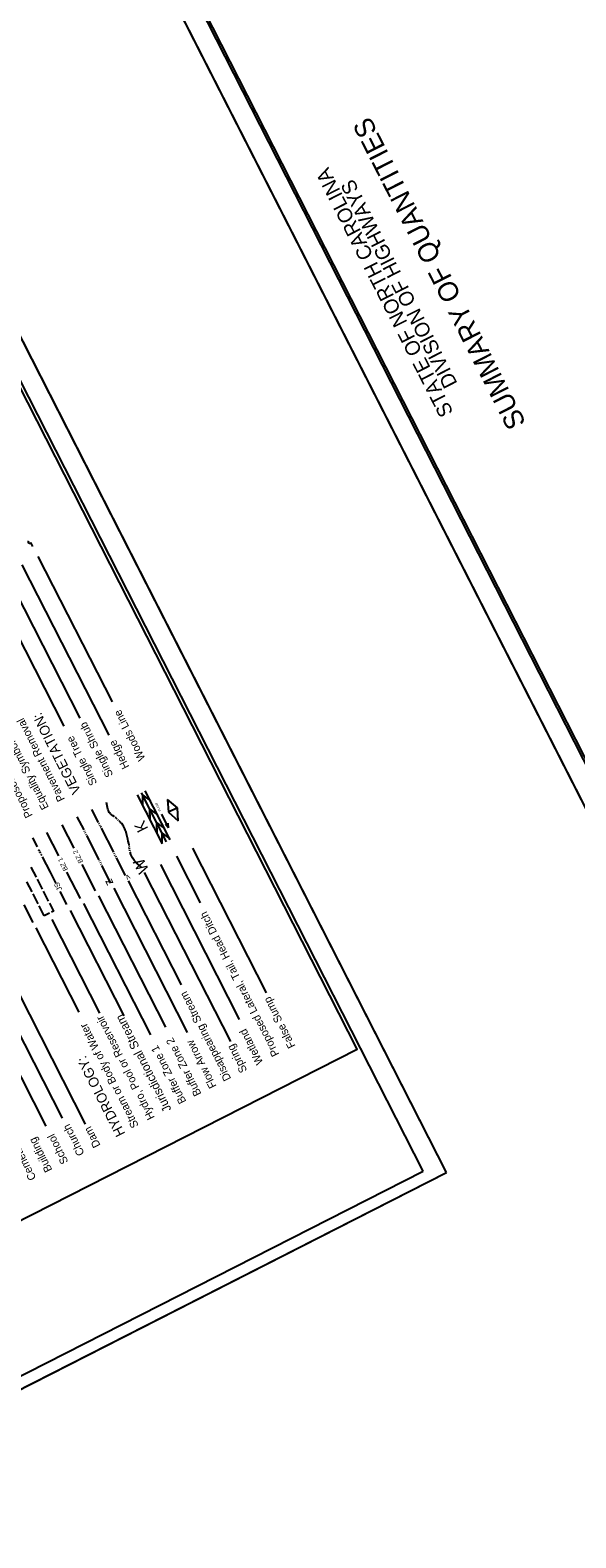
# Model space of a CAD drawing. Extents: x 558484 to 564063, y 513718 to 518374.
# Drawn here: x 561017 to 561623, y 515102 to 516777 of the extents above; entities that cross this region are included whole.
import ezdxf

# ---------------------------------------------------------------- set-up
doc = ezdxf.new("R2010")
doc.units = 0
for name, color, linetype in [('Sheet Cutting Line CELL', 7, 'Continuous'), ('Sheet Plot Border Inside CELL', 7, 'Continuous'), ('Sheet Plot Border Outside CELL', 7, 'Continuous'), ('Sheet Summary CELL', 7, 'Continuous'), ('Sheet Symbology CELL', 7, 'Continuous')]:
    doc.layers.add(name, color=color, linetype=linetype)

msp = doc.modelspace()

# ---------------------------------------------------------------- linework, layer by layer
at = {"layer": 'Sheet Cutting Line CELL'}
for p, q in [((561017.5, 517122.6), (561781.6, 515621.9)), ((561479.4, 515508), (560715.3, 517008.7)), ((560499.1, 515008.9), (561479.4, 515508))]:
    msp.add_line(p, q, dxfattribs=at)
at = {"layer": 'Sheet Plot Border Inside CELL'}
for points in [[(561039.6, 517128.8), (561795.7, 515643.7), (562735.9, 516122.4), (561979.8, 517607.5)], [(561453.5, 515509.4), (560697.4, 516994.5), (559757.1, 516515.8), (560513.2, 515030.7)]]:
    msp.add_lwpolyline(points, close=True, dxfattribs=at)
at = {"layer": 'Sheet Plot Border Outside CELL'}
for points in [[(561017.5, 517122.6), (561781.6, 515621.9), (562761.8, 516121), (561997.8, 517621.7)], [(561479.4, 515508), (560715.3, 517008.7), (559735.1, 516509.6), (560499.1, 515008.9)]]:
    msp.add_lwpolyline(points, close=True, dxfattribs=at)
at = {"layer": 'Sheet Summary CELL'}
msp.add_line((561467.1, 516490.3), (561467.1, 516490.3), dxfattribs=at)
msp.add_lwpolyline([(561047.5, 517118.8), (561728.1, 515782.1), (562663.8, 516258.4), (561983.2, 517595.2)], close=True, dxfattribs=at)
at = {"layer": 'Sheet Symbology CELL'}
for p, q in [((561020.5, 516203.4), (561018.2, 516207.8)), ((561008.3, 516183.2), (561104.8, 515993.7)), ((561026.1, 516192.3), (561108.3, 516030.9)), ((560972.7, 516165.1), (561054.8, 516003.7)), ((560990.5, 516174.2), (561072.7, 516012.8)), ((561168.8, 515875.3), (561141, 515929.9)), ((561172.8, 515877.6), (561145.1, 515932)), ((561164.4, 515873.3), (561136.7, 515927.7)), ((561142.5, 515916.4), (561142.4, 515927.1)), ((561142.4, 515927.1), (561150.8, 515920.9)), ((561180.8, 515913.2), (561169.8, 515922.5)), ((561169.8, 515922.5), (561171, 515908.2)), ((561180.8, 515913.2), (561171, 515908.2)), ((561181.8, 515898.5), (561180.8, 515913.2)), ((561077.2, 515888.5), (561069.7, 515903.1)), ((561093.3, 515896.7), (561085.9, 515911.4)), ((561094.2, 515894.9), (561093.8, 515895.8)), ((561114.1, 515900.6), (561113.3, 515901.2)), ((561115.6, 515899.2), (561114.8, 515899.9)), ((561150.5, 515900.6), (561150.4, 515911.5)), ((561150.4, 515911.5), (561158.8, 515905.2)), ((561158.2, 515885.5), (561158.1, 515896.4)), ((561158.1, 515896.4), (561166.5, 515890)), ((561171.1, 515891), (561163.5, 515905.9)), ((561171.1, 515891), (561170.6, 515896.2)), ((561171, 515908.2), (561181.8, 515898.5)), ((561035.7, 515885.8), (561049, 515859.7)), ((561052.6, 515894.4), (561065.9, 515868.3)), ((561078.1, 515886.7), (561077.6, 515887.6)), ((561079, 515884.9), (561078.5, 515885.8)), ((561079.9, 515883.1), (561079.5, 515884)), ((561094, 515855.5), (561080.4, 515882.2)), ((561095.1, 515893.1), (561094.7, 515894)), ((561096.1, 515891.3), (561095.6, 515892.2)), ((561110.1, 515863.7), (561096.5, 515890.4)), ((561164, 515874.1), (561163.8, 515885)), ((561163.8, 515885), (561172.3, 515878.7)), ((561171.1, 515891), (561167.7, 515894.7)), ((561111, 515861.9), (561110.6, 515862.8)), ((561127.6, 515869.2), (561127.4, 515870.2)), ((561197.5, 515868.3), (561279.3, 515707.7)), ((561018.3, 515847.3), (561023.9, 515836.1)), ((561090, 515820.9), (561075.2, 515850.1)), ((561094.9, 515853.7), (561094.4, 515854.6)), ((561095.8, 515851.9), (561095.3, 515852.8)), ((561096.7, 515850.1), (561096.2, 515851)), ((561107.1, 515829.6), (561097.1, 515849.2)), ((561111.9, 515860.1), (561111.5, 515861)), ((561112.8, 515858.4), (561112.4, 515859.3)), ((561123.3, 515837.8), (561113.3, 515857.5)), ((561161.9, 515850.2), (561249.5, 515678)), ((561179.7, 515859.3), (561206.1, 515807.4)), ((561019.5, 515819.9), (561013.8, 515831)), ((561025.1, 515833.9), (561030.7, 515822.7)), ((561073.1, 515812.3), (561058.2, 515841.5)), ((561126.2, 515832), (561185, 515716.6)), ((561144.1, 515841.1), (561239.6, 515653.5)), ((561026.3, 515806.5), (561020.6, 515817.6)), ((561031.9, 515820.5), (561037.5, 515809.4)), ((561093.3, 515815.3), (561167.6, 515669.3)), ((561110.1, 515823.8), (561191.7, 515663.6)), ((561020.7, 515785.6), (561010.7, 515805.3)), ((561033.1, 515793.1), (561027.4, 515804.3)), ((561038.7, 515796), (561033.1, 515793.1)), ((561061.7, 515799.2), (561121.4, 515681.9)), ((561076.5, 515806.7), (561150.8, 515660.8)), ((561023.7, 515779.8), (561071.3, 515686.3)), ((561041.5, 515788.9), (561094.3, 515685.2)), ((560976.4, 515762.6), (561078.6, 515561.7)), ((560958.5, 515753.5), (561052.8, 515568.4)), ((560940.7, 515744.5), (561034.9, 515559.4))]:
    msp.add_line(p, q, dxfattribs=at)
msp.add_lwpolyline([(559765.1, 516505.8), (560445.6, 515169.1), (561380.4, 515645), (560699.9, 516981.8)], close=True, dxfattribs=at)
for points in [[(561110.9, 515903.1), (561110.5, 515903.4), (561108.7, 515904.7), (561107.8, 515905.3), (561107, 515906.1), (561106.4, 515906.7), (561105.9, 515907.2), (561105.5, 515907.7), (561105.2, 515908.1), (561104.7, 515909), (561104.4, 515909.6), (561104.2, 515910.1), (561103.9, 515910.9), (561103.7, 515911.7), (561102.9, 515915.3), (561102.2, 515918.9)], [(561112.5, 515901.8), (561112.4, 515902), (561111.8, 515902.5)], [(561127.3, 515871.2), (561127.2, 515872), (561126.9, 515873.4), (561126.3, 515876.2), (561125.9, 515878.2), (561125.1, 515881.2), (561124.3, 515884.2), (561123.8, 515885.9), (561123.3, 515887.3), (561122.8, 515888.6), (561122.4, 515889.7), (561122, 515890.6), (561121.6, 515891.4), (561120.9, 515892.8), (561120.3, 515893.8), (561119.8, 515894.5), (561119, 515895.6), (561118.2, 515896.6), (561117.5, 515897.3), (561116.9, 515897.9), (561116.3, 515898.6)], [(561025.5, 515869.7), (561020.3, 515879.9)], [(561127.8, 515867.2), (561127.8, 515867.7), (561127.7, 515868.2)], [(561128.2, 515865.3), (561128.1, 515865.7), (561128, 515866.2)], [(561141.1, 515846.9), (561138.8, 515848.9), (561136.4, 515850.9), (561135.8, 515851.4), (561134.9, 515852.3), (561134.2, 515853.1), (561133.2, 515854.2), (561132.3, 515855.4), (561131.6, 515856.5), (561131, 515857.4), (561130.6, 515858.3), (561130.2, 515859), (561129.6, 515860.4), (561129.2, 515861.4), (561128.9, 515862.2), (561128.6, 515863.4), (561128.4, 515864.3)], [(561039.9, 515841.5), (561031.2, 515858.5)], [(561046.2, 515829), (561039.9, 515841.5)], [(561058, 515805.8), (561050.8, 515820.1)], [(561038.7, 515807.2), (561043.2, 515798.3), (561041, 515797.1)]]:
    msp.add_lwpolyline(points, dxfattribs=at)
msp.add_arc((561016.7, 516208.6), 1.58, 135.4169, 336.2134, dxfattribs=at)
for centre in [(561027.1, 515865.9), (561028.3, 515863.6), (561029.7, 515860.9)]:
    msp.add_ellipse(centre, major_axis=(-0.175, -0.089), ratio=0.938496, dxfattribs=at)

# ---------------------------------------------------------------- texts
at = {"layer": 'Sheet Summary CELL'}
for s, height, p in [('SUMMARY OF QUANTITIES', 21.95, (561568.1, 516340.5)), ('STATE OF NORTH CAROLINA', 16.25, (561487.4, 516352.3)), ('DIVISION OF HIGHWAYS', 16.25, (561492, 516384.5))]:
    msp.add_text(s, height=height, rotation=116.9819, dxfattribs=at).set_placement(p)
at = {"layer": 'Sheet Symbology CELL'}
for s, height, rotation, p in [('Proposed Cable Guiderail', 8.75, 116.9819, (561020.5, 515904.6)), ('Pavement Removal', 8.75, 116.9819, (561056.2, 515922.7)), ('VEGETATION:', 11, 116.9819, (561074.1, 515931.8)), ('Woods Line', 8.75, 116.9819, (561145.5, 515967.9)), ('Single Shrub', 8.75, 116.9819, (561109.8, 515949.7)), ('Equality Symbol', 8.75, 116.9819, (561038.4, 515913.7)), ('Single Tree', 8.75, 116.9819, (561092, 515940.6)), ('Hedge', 8.75, 116.9819, (561127.7, 515958.8)), ('FLOW', 2.59, 116.9819, (561162.9, 515910)), ('K', 12.7, 116.9819, (561148.8, 515890)), ('BZ 2', 5.31, 116.9819, (561076.3, 515853.2)), ('BZ 1', 5.31, 116.9819, (561059.5, 515844.6)), ('W', 12.7, 116.9819, (561149.7, 515844.1)), ('JS', 5.91, 116.9819, (561053.2, 515822.6)), ('z', 10, 296.9819, (561100.4, 515831.8)), ('v', 6.6, 206.7411, (561126.6, 515839.5)), ('Proposed Lateral, Tail, Head Ditch', 8.75, 116.9819, (561294.1, 515639.5)), ('Disappearing Stream', 8.75, 116.9819, (561240.7, 515612.3)), ('False Sump', 8.75, 116.9819, (561312, 515648.6)), ('Hydro, Pool or Reservoir', 8.75, 116.9819, (561155.9, 515569.2)), ('Jurisdictional Stream', 9.646, 116.9819, (561174.4, 515578.2)), ('Stream or Body of Water', 8.75, 116.9819, (561138.1, 515560.1)), ('Wetland', 8.75, 116.9819, (561276.3, 515630.4)), ('Buffer Zone 1', 8.75, 116.9819, (561190.9, 515587)), ('Buffer Zone 2', 8.75, 116.9819, (561207.7, 515595.5)), ('Flow Arrow', 8.75, 116.9819, (561224.5, 515604.1)), ('Spring', 8.75, 116.9819, (561258.5, 515621.4)), ('HYDROLOGY:', 11, 116.9819, (561123.2, 515551.2)), ('Church', 8.75, 116.9819, (561078, 515529.2)), ('Cemetery', 8.75, 116.9819, (561024.4, 515501.9)), ('Building', 8.75, 116.9819, (561042.2, 515511)), ('School', 8.75, 116.9819, (561060, 515520)), ('Dam', 8.75, 116.9819, (561095.7, 515538.2))]:
    msp.add_text(s, height=height, rotation=rotation, dxfattribs=at).set_placement(p)

doc.saveas('drawing.dxf')
